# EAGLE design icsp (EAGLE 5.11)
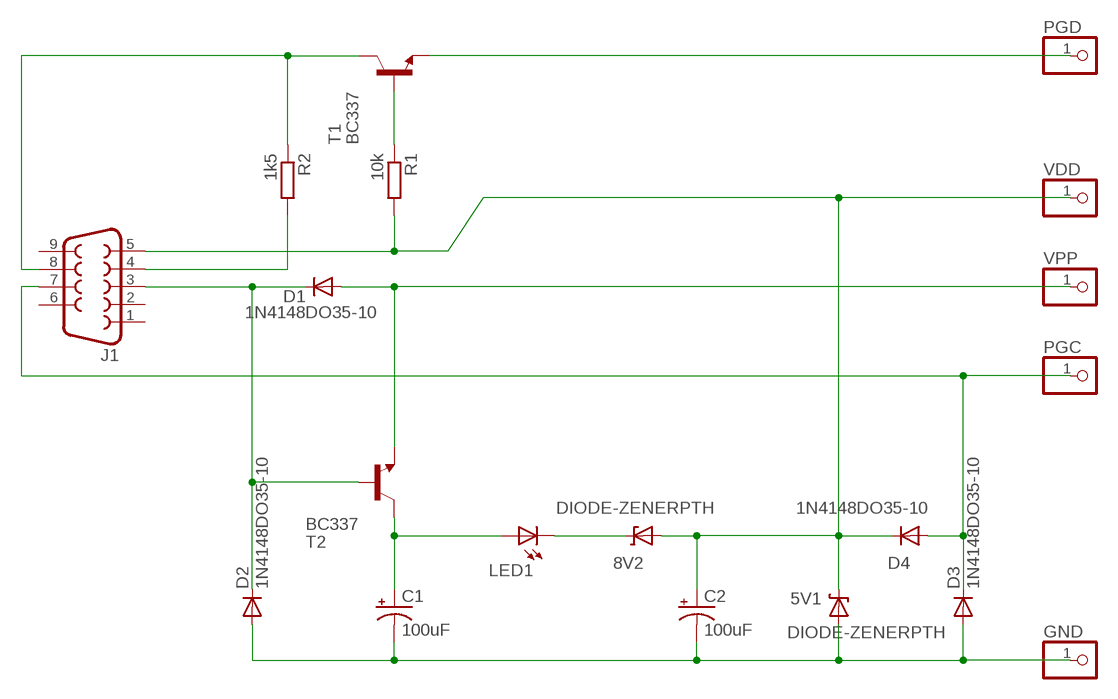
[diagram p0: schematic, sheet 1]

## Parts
5V1  DIODE-ZENERPTH  [DIODE-ZENER]
8V2  DIODE-ZENERPTH  [DIODE-ZENER]
C1  100uF  CPOL-USE5-6  [E5-6]
C2  100uF  CPOL-USE5-6  [E5-6]
D1  1N4148DO35-10  [DO35-10]
D2  1N4148DO35-10  [DO35-10]
D3  1N4148DO35-10  [DO35-10]
D4  1N4148DO35-10  [DO35-10]
GND  PINHD-1X1  [1X01]
J1  DB9  [7457814]
LED1  LED3MM  [LED3MM]
PGC  PINHD-1X1  [1X01]
PGD  PINHD-1X1  [1X01]
R1  10k  R-EU_0207/10  [0207/10]
R2  1k5  R-EU_0207/10  [0207/10]
T1  BC337  [TO92]
T2  BC337  [TO92]
VDD  PINHD-1X1  [1X01]
VPP  PINHD-1X1  [1X01]

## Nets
N$2: J1.4 R2.2
N$3: J1.8 R2.1 T1.3(C)
N$4: R1.1 T1.2(B)
N$6: D1.C D2.C J1.3 T2.2(B)
N$7: D1.A T2.1(E) VPP.1
N$8: C1.+ LED1.A T2.3(C)
N$9: PGD.1 T1.1(E)
N$10: D3.C D4.A J1.7 PGC.1
N$11: 5V1.P$1(C) 8V2.P$2(A) C2.+ D4.C J1.5 R1.2 VDD.1
N$12: 8V2.P$1(C) LED1.K(C)
N$14: 5V1.P$2(A) C1.- C2.- D2.A D3.A GND.1
Unconnected: J1.1 J1.2 J1.6 J1.9

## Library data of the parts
5V1 8V2 = SparkFun:DIODE-ZENER: Zener Diode
C1 C2 = resistor:CPOL-US: POLARIZED CAPACITOR, American symbol
D1-D4 = diode:1N4148: DIODE
GND PGC PGD VDD VPP = pinhead:PINHD-1X1: PIN HEADER
J1 = ADS:DB9: DB9 Connector
LED1 = led:LED: LED
R1 R2 = resistor:R-EU_: RESISTOR, European symbol
T1 T2 = transistor:BC337: NPN TRANSISTOR

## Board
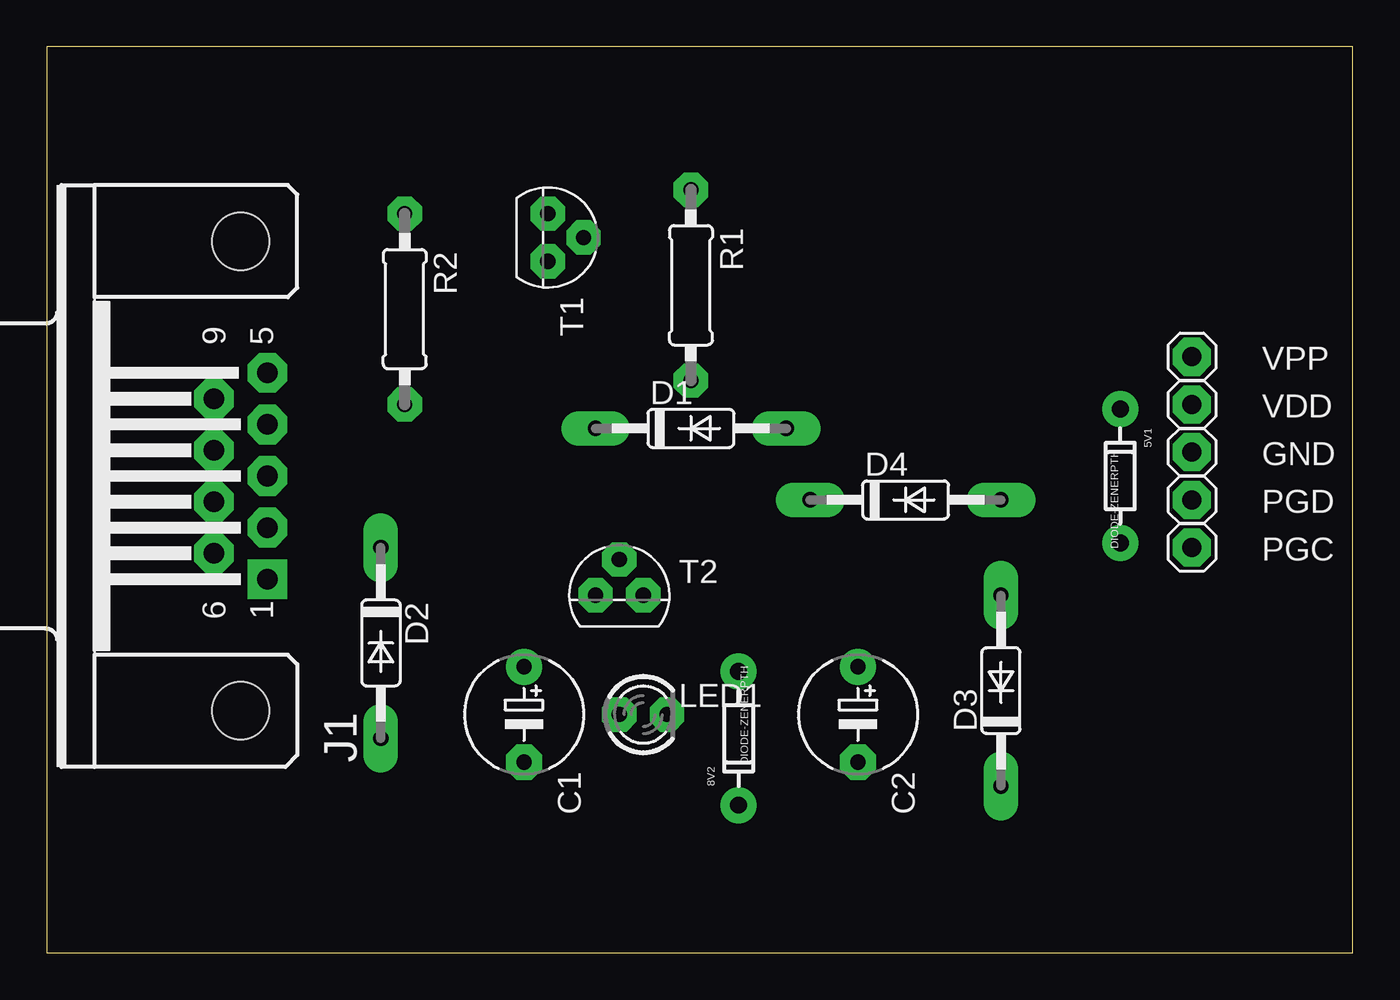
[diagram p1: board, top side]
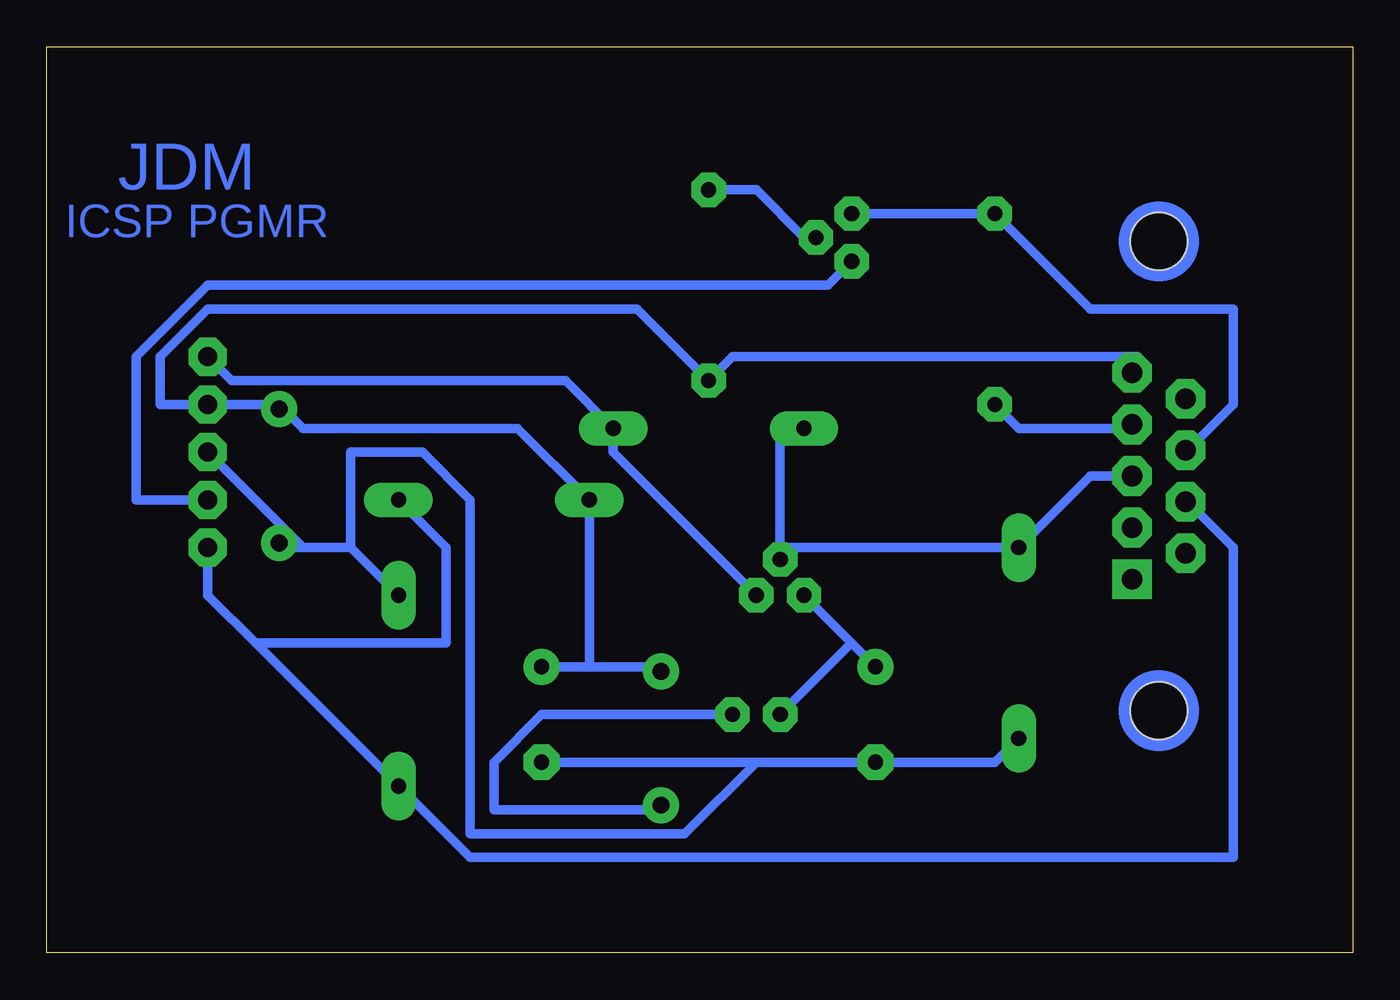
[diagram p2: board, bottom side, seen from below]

Size 69.52 x 48.25 mm. Coordinates in mm from the lower left corner, seen from the top.
Outline: 0,0 69.52,0 69.52,48.25 0,48.25 0,0
Copper layers (1*16): Top 0.035mm / dielectric 1.5mm / Bottom 0.035mm
Design rules "default *": minimum track width 20mil, minimum drill 24mil, track to track 10mil, track to pad 10mil, pad to pad 10mil, via to via 10mil, smd to smd 8mil, copper to edge 40mil, drill to drill 8mil, minimum pad ring 20mil, minimum via ring 20mil, stop-mask expansion 4mil, vias tented up to drill 0mil, thermal gap 10mil

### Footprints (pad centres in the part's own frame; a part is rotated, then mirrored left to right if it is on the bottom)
DIODE-ZENER = drill 0.9 round: P$1 -3.556,0; P$2 3.556,0
E5-6 = drill 0.813 pad 1.905 round: + -2.54,0 | drill 0.813 pad 1.905 octagon: - 2.54,0
DO35-10 = drill 0.813 long: A 5.08,0; C -5.08,0
1X01 = drill 1.016 octagon: 1 0,0
7457814 = drill 1.092 pad 1.778 square: 1 -5.486,-7.925 | drill 1.092 pad 1.778 octagon: 2 -2.743,-7.925; 3 0,-7.925; 4 2.743,-7.925; 5 5.486,-7.925; 6 -4.115,-5.08; 7 -1.372,-5.08; 8 1.372,-5.08; 9 4.115,-5.08 | hole 3.048: -12.497,-6.502; 12.497,-6.502
LED3MM = drill 0.813 octagon: A -1.27,0; K 1.27,0
0207/10 = drill 0.813 octagon: 1 -5.08,0; 2 5.08,0
TO92 = drill 0.813 octagon: 1 1.27,0; 2 0,1.905; 3 -1.27,0

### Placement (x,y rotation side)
5V1  57.15,25.4 270 top
8V2  36.83,11.43 90 top
C1  25.4,12.7 270 top
C2  43.18,12.7 270 top
D1  34.29,27.94 0 top
D2  17.78,16.51 270 top
D3  50.8,13.97 90 top
D4  45.72,24.13 0 top
GND  60.96,26.67 0 top
J1  3.81,25.4 90 top
LED1  31.75,12.7 0 top
PGC  60.96,21.59 0 top
PGD  60.96,24.13 0 top
R1  34.29,35.56 270 top
R2  19.05,34.29 270 top
T1  26.67,38.1 270 top
T2  30.48,19.05 0 top
VDD  60.96,29.21 0 top
VPP  60.96,31.75 0 top

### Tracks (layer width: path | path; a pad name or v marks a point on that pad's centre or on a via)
N$2
  Bottom 0.508: R2.2 17.78,27.94 12.7,27.94 J1.4
N$3
  Bottom 0.508: T1.3 R2.1 13.97,34.29 6.35,34.29 6.35,29.21 8.89,26.67 J1.8
N$4
  Bottom 0.508: R1.1 31.75,40.64 29.21,38.1 T1.2
N$6
  Bottom 0.508: 30.48,21.59 30.48,27.94 D1.C | J1.3 13.97,25.4 D2.C 30.48,21.59 | 30.48,21.59 T2.2
N$7
  Bottom 0.508: T2.1 39.37,26.67 D1.A 41.91,30.48 59.69,30.48 VPP.1
N$8
  Bottom 0.508: C1.+ 26.67,16.51 | 26.67,16.51 T2.3 | 26.67,16.51 LED1.A
N$9
  Bottom 0.508: T1.1 27.94,35.56 60.96,35.56 64.77,31.75 64.77,24.13 PGD.1
N$10
  Bottom 0.508: 58.42,16.51 60.96,19.05 PGC.1 | 58.42,16.51 D3.C 46.99,5.08 6.35,5.08 6.35,21.59 8.89,24.13 J1.7 | D4.A 48.26,21.59 48.26,16.51 58.42,16.51
N$11
  Bottom 0.508: J1.5 11.43,31.75 33.02,31.75 R1.2 38.1,34.29 60.96,34.29 63.5,31.75 63.5,29.21 VDD.1 57.15,29.21 | 40.64,15.24 D4.C 44.45,27.94 55.88,27.94 57.15,29.21 | 40.64,15.24 C2.+ | 40.64,15.24 36.83,15.24 8V2.P$2 | 57.15,29.21 5V1.P$1
N$12
  Bottom 0.508: LED1.K 43.18,12.7 45.72,10.16 45.72,7.62 36.83,7.62 8V2.P$1
N$14
  Bottom 0.508: 53.34,21.59 D3.A | 55.88,21.59 57.15,21.59 5V1.P$2 | 53.34,21.59 55.88,21.59 | 55.88,21.59 GND.1 | D2.A 19.05,10.16 C1.- 31.75,10.16 | 31.75,10.16 C2.- | 53.34,21.59 53.34,26.67 49.53,26.67 46.99,24.13 46.99,6.35 35.56,6.35 31.75,10.16

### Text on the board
Bottom: JDM | ICSP PGMR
